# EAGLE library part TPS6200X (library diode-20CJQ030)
Ti's TPS6200x High efficiency Step-Down low power DC-DC Converter Description: The TPS6200x devices are a family of low-noise synchronous step-down dc-dc converters that are ideally suited for systems powered from a 1-cell Li-ion battery or from a 2- to 3-cell NiCd, NiMH, or alkaline battery. The TPS6200x operates typically down to an input voltage of 1.8 V, with a specified minimum input voltage of 2 V. The TPS6200x is a synchronous current-mode PWM converter with integrated N- and P-channel power MOSFET switches. Synchronous rectification is used to increase efficiency and to reduce external component count. To achieve the highest efficiency over a wide load current range, the converter enters a power-saving pulse-frequency modulation (PFM) mode at light load currents. Operating frequency is typically 750 kHz, allowing the use of small inductor and capacitor values. The device can be synchronized to an external clock signal in the range of 500 kHz to 1 MHz. For low-noise operation, the converter can be operated in the PWM mode and the internal antiringing switch reduces noise and EMI. In the shutdown mode, the current consumption is reduced to less than 1 uA. The TPS6200x is available in the 10-pin (DGS) microsmall outline package (MSOP). The TPS62000 is also available in a 12-pin, 1,85 mm x 1,3 mm NanoStar chip scale package (YEG). The devices operate over a free-air temperature range of -40°C to 85°C. Features: High-Efficiency Synchronous Step-Down Converter With Greater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
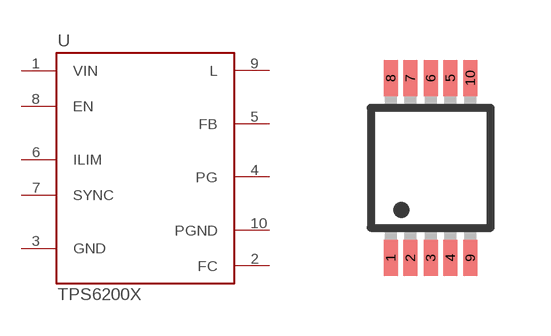
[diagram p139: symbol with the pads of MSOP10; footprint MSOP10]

Designator prefix U

## TPS6200X-DGS  [MSOP10]
1  VIN  pwr
2  FC  pwr
3  GND  pas
4  PG  out
5  FB  in
6  ILIM  in
7  SYNC  in
8  EN  in
9  L
10  PGND  pwr

## Footprint MSOP10 (pad centres in mm)
MSOP10
smd 0.35 x 0.9: 1 -1,-2.25; 2 -0.51,-2.25; 3 0,-2.25; 4 0.49,-2.25; 5 0.49,2.25; 6 0,2.25; 7 -0.51,2.25; 8 -1,2.25; 9 0.99,-2.25; 10 0.99,2.25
